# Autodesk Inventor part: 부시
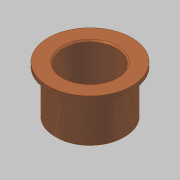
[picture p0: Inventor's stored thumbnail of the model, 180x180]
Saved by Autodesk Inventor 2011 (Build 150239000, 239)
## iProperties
Created: 2013-06
Part Number: 부시
Document SubType Name: Modeling
Designer: SeoGD™[esajin.kr]
Density: 1 g/cm^3
Author: SeoGD™[esajin.kr]
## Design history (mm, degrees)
sketch "스케치1"
  geometry: C1 r 31 at (0, 0) reference; C2 r 25 at (0, 0) reference; C3 r 30 at (0, 0) reference; 1 further point
  node "참조1"
  node "참조2"
  node "참조4"
extrude "돌출1" new body sketch "스케치1" distance "d0" = 3; taper "d1" = 0 deg
extrude "돌출2" join sketch "스케치1" distance "d2" = 35; taper "d3" = 0 deg
chamfer "모따기1" distance "d6" = 1; stored, may be unused: second distance "d7" = 2, angle "d8" = 45 deg
sketch "스케치3"
  geometry: C1 r 19 at (0, 0); 1 further point
  constraints: 1 centre point, 1 coincident
  dimensions: "d13" = 38 diameter of C1
extrude "돌출4" cut sketch "스케치3" stored distance "d14" = 10; taper "d15" = 0 deg
chamfer "모따기3" distance "d16" = 1; stored, may be unused: second distance "d17" = 2, angle "d18" = 45 deg
node "솔리드1"
